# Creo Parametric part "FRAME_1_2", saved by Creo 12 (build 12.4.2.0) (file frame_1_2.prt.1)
Units: Custom; MM, KILOGRAM, SECS

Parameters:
  PTC_WM_ITERATION = "0"
  PTC_WM_VERSION = "-.0"
  PTC_WM_LIFECYCLE_STATE = "In Work"
  PTC_WM_LIFECYCLE = "MO_CADDocument"
  PTC_WM_CREATED_BY = "Maximilian Roepper (Z0017RMS: MO)"
  PTC_WM_CREATED_ON = "18-Sep-26 11:36:42 AM"
  PTC_WM_MODIFIED_BY = "Maximilian Roepper (Z0017RMS: MO)"
  PTC_WM_MODIFIED_ON = "18-Sep-26 11:36:46 AM"
  PDMLINKNUMBER = "PDM000071454854"
  PTC_WM_NAME = "frame_1_2.prt"
  PTC_WM_NUMBER = "PDM000071454854"

Other parameters: WEIGHT, WEIGHT_FACTOR, WEIGHT_ADD, _MASS_TEMP, _DIFF_TEMP, MC_ERRORS, SUPPLIER

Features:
  1. coordinate system
  2. datum plane "PRT_YZ"
  3. datum plane "PRT_XY"
  4. datum plane "PRT_XZ"
  5. coordinate system
  6. datum axis
  7. datum axis
  8. datum axis
  9. coordinate system
  10. imported feature

Other named items: PRT, SIEMENS_MO, DRW_VIEW_ORG, PRT_X, PRT_Y, PRT_Z, CS0, ROUGH_GROB

Layers: 00_STD_CSYS-KSYS, 01_STD_PLANES-EBENEN, 02_STD_AXES-ACHSEN, 03_STD_CSYS-KSYS, 24_IMPORT_FEAT-IMPORT_KE

Surfaces: 276 plane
